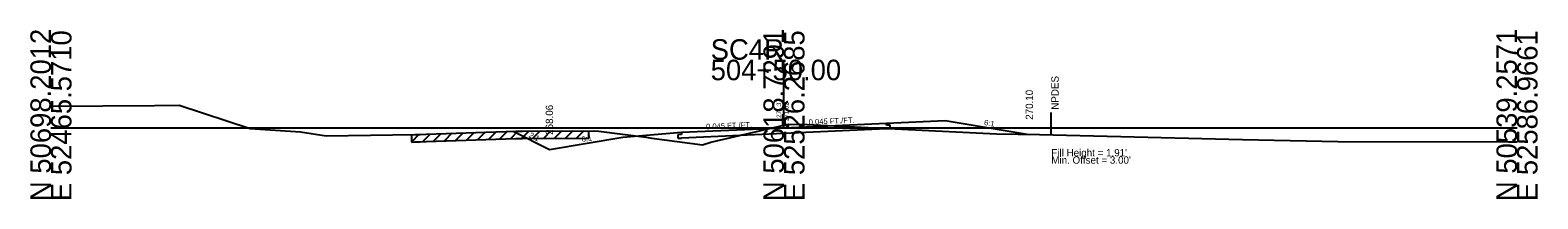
# Model space of a CAD drawing. Extents: x 7498 to 13027, y 90095 to 109625.
# Drawn here: x 8521.2 to 8726.8, y 94595.5 to 94618.5 of the extents above; entities that cross this region are included whole.
import ezdxf

# ---------------------------------------------------------------- set-up
doc = ezdxf.new("R2010")
doc.units = 0
for name, color, linetype in [('Level 10', 7, 'Continuous'), ('Level 11', 7, 'Continuous'), ('Level 12', 7, 'Continuous'), ('Level 32', 7, 'Continuous'), ('Level 33', 7, 'Continuous'), ('Level 50', 7, 'Continuous'), ('Level 55', 7, 'Continuous'), ('Level 59', 7, 'Continuous'), ('Level 6', 7, 'Continuous'), ('Level 60', 7, 'Continuous'), ('Level 61', 7, 'Continuous'), ('Level 63', 7, 'Continuous'), ('Level 7', 7, 'Continuous')]:
    doc.layers.add(name, color=color, linetype=linetype)

msp = doc.modelspace()

# ---------------------------------------------------------------- linework, layer by layer
at = {"layer": 'Level 11'}
for p, q in [((8637.99, 94605.51), (8637.99, 94605.81)), ((8638.49, 94605.53), (8637.99, 94605.51)), ((8638.49, 94605.05), (8638.49, 94605.53)), ((8609.99, 94604.25), (8609.49, 94604.22)), ((8609.49, 94604.22), (8609.49, 94603.74)), ((8609.49, 94603.74), (8609.99, 94603.77)), ((8609.99, 94604.55), (8609.99, 94604.25)), ((8637.99, 94605.03), (8638.49, 94605.05))]:
    msp.add_line(p, q, dxfattribs=at)
at = {"layer": 'Level 12'}
for p, q in [((8623.99, 94604.4), (8609.99, 94603.77)), ((8637.99, 94605.03), (8623.99, 94604.4))]:
    msp.add_line(p, q, dxfattribs=at)
at = {"layer": 'Level 55'}
msp.add_line((8660.46, 94604.26), (8660.46, 94607.26), dxfattribs=at)
at = {"layer": 'Level 59'}
for p, q in [((8623.99, 94605.18), (8637.99, 94605.81)), ((8609.99, 94604.55), (8623.99, 94605.18))]:
    msp.add_line(p, q, dxfattribs=at)
at = {"layer": 'Level 6'}
for p, q in [((8637.99, 94605.81), (8645.99, 94606.17)), ((8601.99, 94603.88), (8609.99, 94604.55))]:
    msp.add_line(p, q, dxfattribs=at)
at = {"layer": 'Level 60'}
for p, q in [((8523.99, 94608.13), (8538.12, 94608.23)), ((8538.12, 94608.23), (8541.5, 94608.26)), ((8541.5, 94608.26), (8551.16, 94605.06)), ((8614, 94603.19), (8623.99, 94605.53)), ((8623.99, 94605.53), (8624.67, 94605.68)), ((8624.67, 94605.68), (8627.14, 94605.62)), ((8627.14, 94605.62), (8652.97, 94604.35)), ((8551.16, 94605.06), (8558.05, 94604.63)), ((8558.05, 94604.63), (8561.55, 94604.07)), ((8561.55, 94604.07), (8573.61, 94604.23)), ((8573.61, 94604.23), (8574.34, 94604.26)), ((8574.34, 94604.26), (8575.19, 94604.29)), ((8575.19, 94604.29), (8587.41, 94604.7)), ((8587.41, 94604.7), (8588.34, 94604.71)), ((8588.34, 94604.71), (8598.13, 94604.76)), ((8598.13, 94604.76), (8598.74, 94604.7)), ((8598.74, 94604.7), (8605.17, 94603.89)), ((8605.17, 94603.89), (8605.98, 94603.76)), ((8605.98, 94603.76), (8612.87, 94602.84)), ((8652.97, 94604.35), (8658.83, 94604.23)), ((8658.83, 94604.23), (8686.53, 94603.58)), ((8686.53, 94603.58), (8699.53, 94603.28)), ((8699.53, 94603.28), (8722.81, 94603.25)), ((8722.81, 94603.25), (8723.99, 94603.25)), ((8612.87, 94602.84), (8614, 94603.19))]:
    msp.add_line(p, q, dxfattribs=at)
at = {"layer": 'Level 61'}
for p, q in [((8574.19, 94604.25), (8573.16, 94603.22)), ((8573.16, 94604.22), (8573.16, 94603.22)), ((8573.16, 94603.22), (8573.61, 94603.23)), ((8573.61, 94603.23), (8574.34, 94603.26)), ((8574.34, 94603.26), (8575.19, 94603.29)), ((8575.7, 94604.3), (8574.67, 94603.27)), ((8575.19, 94603.29), (8587.41, 94603.7)), ((8577.2, 94604.36), (8576.17, 94603.32)), ((8578.7, 94604.41), (8577.67, 94603.37)), ((8580.21, 94604.46), (8579.17, 94603.42)), ((8581.71, 94604.51), (8580.67, 94603.47)), ((8583.21, 94604.56), (8582.17, 94603.52)), ((8584.71, 94604.61), (8583.67, 94603.57)), ((8586.21, 94604.66), (8585.17, 94603.62)), ((8587.7, 94604.7), (8586.68, 94603.68)), ((8587.41, 94603.7), (8588.34, 94603.71)), ((8589.18, 94604.71), (8588.18, 94603.71)), ((8588.34, 94603.71), (8597.39, 94603.76)), ((8590.68, 94604.72), (8589.68, 94603.72)), ((8592.19, 94604.73), (8591.18, 94603.72)), ((8593.69, 94604.74), (8592.68, 94603.73)), ((8595.19, 94604.75), (8594.18, 94603.74)), ((8596.69, 94604.75), (8595.68, 94603.75)), ((8597.39, 94603.76), (8597.39, 94604.76))]:
    msp.add_line(p, q, dxfattribs=at)
at = {"layer": 'Level 63'}
for p, q in [((8623.99, 94605.16), (8623.99, 94614.46)), ((8523.99, 94605.16), (8623.99, 94605.16)), ((8623.99, 94605.16), (8723.99, 94605.16))]:
    msp.add_line(p, q, dxfattribs=at)
at = {"layer": 'Level 7'}
for p, q in [((8645.99, 94606.17), (8657.46, 94604.26)), ((8587.05, 94604.69), (8591.99, 94602.21)), ((8591.99, 94602.21), (8601.99, 94603.88))]:
    msp.add_line(p, q, dxfattribs=at)

# ---------------------------------------------------------------- texts
at = {"layer": 'Level 10'}
msp.add_text('271.37', height=0.6, rotation=90, dxfattribs=at).set_placement((8623.59, 94606.53))
at = {"layer": 'Level 32'}
for s, rotation, p in [('0.045 FT./FT.', 2.5766, (8613.38, 94604.95)), ('0.045 FT./FT.', 2.5766, (8627.38, 94605.58)), ('6:1', 350.5377, (8651.24, 94605.55)), ('2:1', 333.435, (8589.12, 94603.93)), ('6:1', 9.4623, (8596.43, 94603.21))]:
    msp.add_text(s, height=0.75, rotation=rotation, dxfattribs=at).set_placement(p)
at = {"layer": 'Level 33'}
for s, p in [('270.10', (8657.96, 94606.26)), ('268.06', (8592.49, 94604.21))]:
    msp.add_text(s, height=1, rotation=90, dxfattribs=at).set_placement(p)
at = {"layer": 'Level 50'}
msp.add_text(' NPDES', height=1, rotation=90, dxfattribs=at).set_placement((8661.46, 94607.26))
for s, p in [("Fill Height = 1.91' ", (8660.46, 94601.26)), ("Min. Offset = 3.00' ", (8660.46, 94600.26))]:
    msp.add_text(s, height=1, dxfattribs=at).set_placement(p)
at = {"layer": 'Level 59'}
msp.add_text(' 271.02', height=0.6, rotation=90, dxfattribs=at).set_placement((8624.61, 94605.87))
at = {"layer": 'Level 63'}
for s, p in [('N 50698.2012', (8523.99, 94595.16)), ('E 52465.5710', (8526.79, 94595.16)), ('N 50618.7291', (8623.99, 94595.16)), ('E 52526.2685', (8626.79, 94595.16)), ('N 50539.2571', (8723.99, 94595.16)), ('E 52586.9661', (8726.79, 94595.16))]:
    msp.add_text(s, height=2.8, rotation=90, dxfattribs=at).set_placement(p)
for s, p in [('SC4R', (8613.99, 94614.46)), ('504+50.00', (8613.99, 94611.66))]:
    msp.add_text(s, height=2.8, dxfattribs=at).set_placement(p)

doc.saveas('drawing.dxf')
